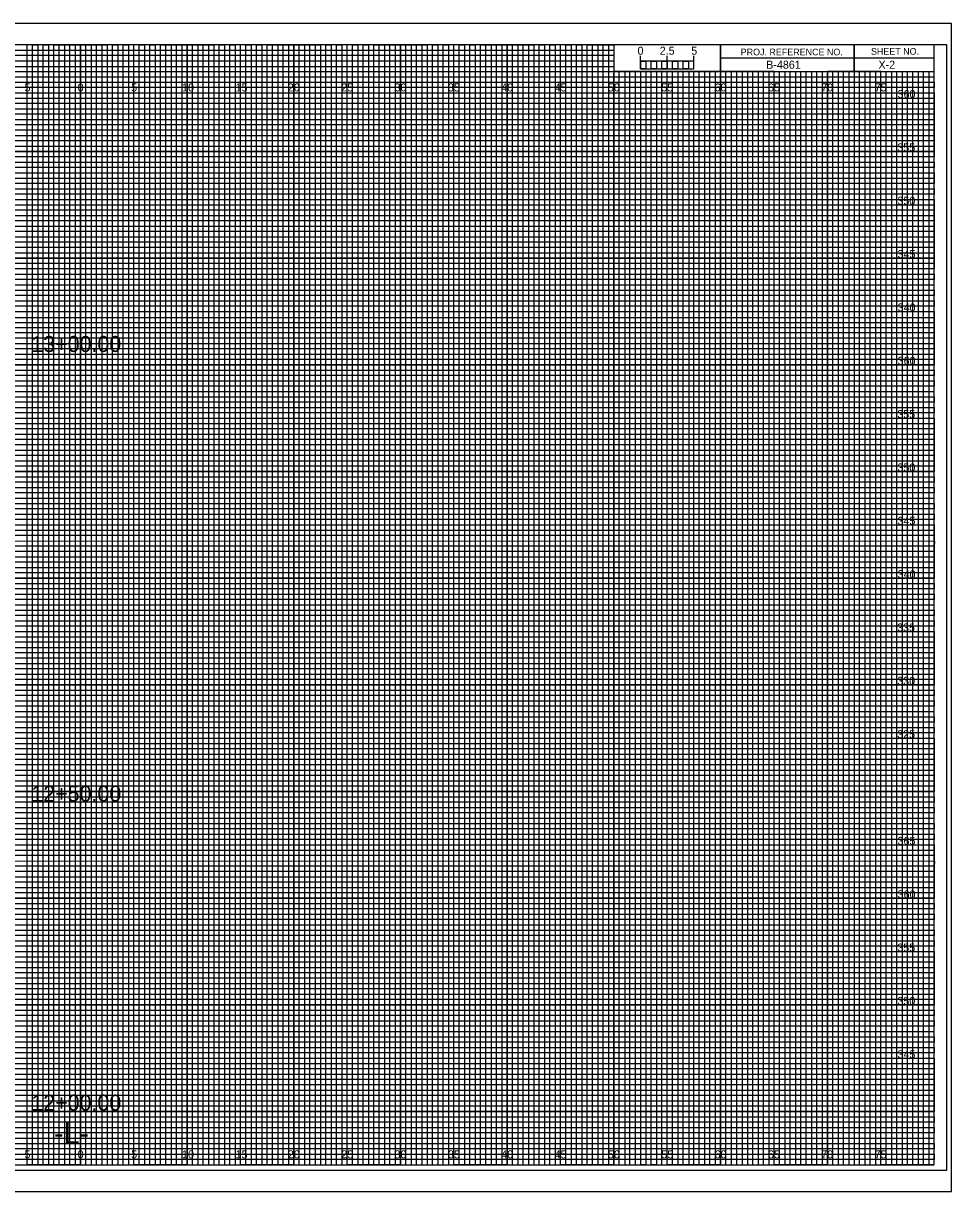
# Model space of a CAD drawing. Extents: x -7 to 266, y -5 to 437.
# Drawn here: x 74.6 to 161.7, y 107.5 to 217 of the extents above; entities that cross this region are included whole.
import ezdxf

# ---------------------------------------------------------------- set-up
doc = ezdxf.new("R2010")
doc.units = 0
for name, color, linetype in [('Exist XS Center Line Elevation Label', 7, 'Continuous'), ('Exist XS Ground Line', 7, 'Continuous'), ('Prop XS Dump Level', 7, 'Continuous'), ('Prop XS EOT Tick Mark', 7, 'Continuous'), ('Prop XS Finish Grade', 7, 'Continuous'), ('Prop XS Finish Grade Concrete', 7, 'Continuous'), ('Prop XS Finish Grade Earthwork', 7, 'Continuous'), ('Prop XS Finish Grade Pavement', 7, 'Continuous'), ('Prop XS Geopak Shape', 7, 'Continuous'), ('Prop XS Hydro Elevations', 7, 'Continuous'), ('Prop XS Pvmt Edge Slope', 7, 'Continuous'), ('Prop XS SE Text', 7, 'Continuous'), ('Prop XS Side Slope Text', 7, 'Continuous'), ('Prop XS SS Elevation Text', 7, 'Continuous'), ('Prop XS Subgrade Earthwork', 7, 'Continuous'), ('Prop XSC Text', 7, 'Continuous'), ('Typical Guardrail CELL', 7, 'Continuous')]:
    doc.layers.add(name, color=color, linetype=linetype)

msp = doc.modelspace()

# ---------------------------------------------------------------- linework, layer by layer
at = {"layer": 'Exist XS Center Line Elevation Label'}
for points in [[(72.5, 110), (77.5, 110), (77.5, 215), (82.5, 215), (82.5, 110), (87.5, 110), (87.5, 215), (92.5, 215), (92.5, 110), (97.5, 110), (97.5, 215), (102.5, 215), (102.5, 110), (107.5, 110), (107.5, 215), (112.5, 215), (112.5, 110), (117.5, 110), (117.5, 215), (122.5, 215), (122.5, 110), (127.5, 110), (127.5, 215), (129.97, 215), (130, 215), (130, 212.5), (132.5, 212.5), (132.5, 110), (137.5, 110), (137.5, 212.5), (142.5, 212.5), (142.5, 110), (147.5, 110), (147.5, 212.5), (152.5, 212.5), (152.5, 110), (157.5, 110), (157.5, 212.5)], [(0, 212.5), (137.5, 212.5)], [(0, 202.5), (160, 202.5), (160, 207.5), (0, 207.5)], [(0, 192.5), (160, 192.5), (160, 197.5), (0, 197.5)], [(0, 182.5), (160, 182.5), (160, 187.5), (0, 187.5)], [(0, 172.5), (160, 172.5), (160, 177.5), (0, 177.5)], [(0, 162.5), (160, 162.5), (160, 167.5), (0, 167.5)], [(0, 152.5), (160, 152.5), (160, 157.5), (0, 157.5)], [(0, 142.5), (160, 142.5), (160, 147.5), (0, 147.5)], [(0, 132.5), (160, 132.5), (160, 137.5), (0, 137.5)], [(0, 122.5), (160, 122.5), (160, 127.5), (0, 127.5)], [(0, 112.5), (160, 112.5), (160, 117.5), (0, 117.5)]]:
    msp.add_lwpolyline(points, dxfattribs=at)
at = {"layer": 'Exist XS Ground Line'}
for p, q in [((75, 215), (70, 215)), ((75, 110), (75, 215)), ((85, 215), (80, 215)), ((80, 215), (80, 110)), ((85, 110), (85, 215)), ((95, 215), (90, 215)), ((90, 215), (90, 110)), ((95, 110), (95, 215)), ((105, 215), (100, 215)), ((100, 215), (100, 110)), ((105, 110), (105, 215)), ((115, 215), (110, 215)), ((110, 215), (110, 110)), ((115, 110), (115, 215)), ((125, 215), (120, 215)), ((120, 215), (120, 110)), ((125, 110), (125, 215)), ((130, 215), (130, 110)), ((135, 110), (135, 212.5)), ((145, 212.5), (140, 212.5)), ((140, 212.5), (140, 110)), ((145, 110), (145, 212.5)), ((155, 212.5), (150, 212.5)), ((150, 212.5), (150, 110)), ((155, 110), (155, 212.5)), ((80, 110), (75, 110)), ((90, 110), (85, 110)), ((100, 110), (95, 110)), ((110, 110), (105, 110)), ((120, 110), (115, 110)), ((130, 110), (125, 110)), ((140, 110), (135, 110)), ((150, 110), (145, 110)), ((160, 110), (155, 110)), ((160, 110), (160, 110))]:
    msp.add_line(p, q, dxfattribs=at)
for points in [[(0, 210), (160, 210), (160, 205), (0, 205)], [(0, 200), (160, 200), (160, 195), (0, 195)], [(0, 190), (160, 190), (160, 185), (0, 185)], [(0, 180), (160, 180), (160, 175), (0, 175)], [(0, 170), (160, 170), (160, 165), (0, 165)], [(0, 160), (160, 160), (160, 155), (0, 155)], [(0, 150), (160, 150), (160, 145), (0, 145)], [(0, 140), (160, 140), (160, 135), (0, 135)], [(0, 130), (160, 130), (160, 125), (0, 125)], [(0, 120), (160, 120), (160, 115), (0, 115)]]:
    msp.add_lwpolyline(points, dxfattribs=at)
at = {"layer": 'Prop XS Finish Grade'}
for p, q in [((75, 110), (75, 215)), ((80, 110), (80, 215)), ((85, 110), (85, 215)), ((90, 110), (90, 215)), ((95, 110), (95, 215)), ((100, 110), (100, 215)), ((105, 110), (105, 215)), ((110, 110), (110, 215)), ((115, 110), (115, 215)), ((120, 110), (120, 215)), ((125, 110), (125, 215)), ((130, 110), (130, 212.34)), ((135, 110), (135, 212.34)), ((140, 110), (140, 212.34)), ((145, 110), (145, 212.34)), ((150, 110), (150, 212.34)), ((155, 110), (155, 212.34)), ((0, 210), (160, 210)), ((0, 205), (160, 205)), ((0, 200), (160, 200)), ((0, 195), (160, 195)), ((0, 190), (160, 190)), ((0, 185), (160, 185)), ((0, 180), (160, 180)), ((0, 175), (160, 175)), ((0, 170), (160, 170)), ((0, 165), (160, 165)), ((0, 160), (160, 160)), ((0, 155), (160, 155)), ((0, 150), (160, 150)), ((0, 145), (160, 145)), ((0, 140), (160, 140)), ((0, 135), (160, 135)), ((0, 130), (160, 130)), ((0, 125), (160, 125)), ((0, 120), (160, 120)), ((0, 115), (160, 115))]:
    msp.add_line(p, q, dxfattribs=at)
at = {"layer": 'Prop XS Finish Grade Earthwork'}
msp.add_lwpolyline([(-6.7, 107.5), (161.65, 107.5), (161.65, 217), (-6.7, 217)], close=True, dxfattribs=at)
at = {"layer": 'Prop XS Hydro Elevations'}
for p, q in [((152.5, 215), (152.5, 212.5)), ((152.5, 212.5), (152.5, 215)), ((160, 213.75), (140, 213.75)), ((140, 213.75), (140, 212.5)), ((140, 212.5), (160, 212.5))]:
    msp.add_line(p, q, dxfattribs=at)
for points in [[(160, 215), (0, 215), (0, 110), (160, 110)], [(140, 215), (130, 215), (130, 212.52), (140, 212.52)], [(160, 215), (140, 215), (140, 212.5), (160, 212.5)]]:
    msp.add_lwpolyline(points, close=True, dxfattribs=at)
at = {"layer": 'Prop XS Pvmt Edge Slope'}
msp.add_lwpolyline([(-5.4, 109.5), (161.2, 109.5), (161.2, 215), (-5.4, 215)], close=True, dxfattribs=at)
at = {"layer": 'Prop XS SE Text'}
for p, q in [((0, 214.5), (130, 214.5)), ((130, 213.99), (0, 213.99)), ((130, 214.5), (130, 213.99)), ((0, 213.5), (130, 213.5)), ((130, 212.94), (0, 212.94)), ((130, 213.5), (130, 212.94)), ((0, 212), (160, 212))]:
    msp.add_line(p, q, dxfattribs=at)
for points in [[(0, 211.5), (135, 211.5), (160, 211.5), (160, 211), (0, 211)], [(0, 210.5), (160, 210.5), (160, 209.5), (0, 209.5)], [(0, 209), (160, 209), (160, 208.5), (0, 208.49)], [(0, 208), (160, 208), (160, 207), (0, 207)], [(0, 206.5), (160, 206.5), (160, 206), (0, 206)], [(0, 205.5), (160, 205.5), (160, 204.5), (0, 204.5)], [(0, 204), (160, 204), (160, 203.5), (0, 203.5)], [(0, 203), (160, 203), (160, 202), (0, 202)], [(0, 201.5), (160, 201.5), (160, 201), (0, 201)], [(0, 200.5), (160, 200.5), (160, 199.5), (0, 199.5)], [(0, 199), (160, 199), (160, 198.5), (0, 198.5)], [(0, 198), (160, 198), (160, 196.97), (160, 196.5), (160, 196), (0, 196)], [(0, 197), (160, 197), (160, 196.5), (0, 196.5)], [(0, 195.5), (160, 195.5), (160, 194.5), (0, 194.52)], [(0, 194.52), (160, 194.5), (160, 194), (0, 194)], [(0, 193.5), (160, 193.5), (160, 193), (0, 193)], [(0, 192), (160, 192), (160, 191.5), (0, 191.5)], [(0, 191), (160, 191), (160, 190.5), (0, 190.5)], [(-0.04, 189.44), (160, 189.44), (160, 188.94), (-0.04, 188.94)], [(0, 188.5), (160, 188.5), (160, 188), (0, 188)], [(0, 187), (160, 187), (160, 186.5), (0, 186.5)], [(0, 186), (160, 186), (160, 185.5), (0, 185.5)], [(0, 184.5), (160, 184.5), (160, 184), (0, 184)], [(0, 183.5), (160, 183.5), (160, 183), (0, 183)], [(0, 182), (160, 182), (160, 181.5), (0, 181.5)], [(0, 181), (160, 181), (160, 180.5), (0, 180.5)], [(0, 179.5), (160, 179.5), (160, 178.99), (0, 179)], [(0, 178.5), (160, 178.5), (160, 178), (0, 178)], [(0, 177), (160, 177), (160, 176.5), (0, 176.5)], [(0, 176), (160, 176), (160, 175.5), (0, 175.5)], [(0, 174.5), (160, 174.5), (160, 174), (0, 174)], [(0, 173.5), (160, 173.5), (160, 173), (0, 173)], [(0, 172), (160, 172), (160, 171.5), (0, 171.5)], [(0, 171), (160, 171), (160, 170.5), (0, 170.5)], [(0, 169.5), (160, 169.5), (160, 169), (0, 169)], [(0, 168.5), (160.03, 168.46), (160, 168), (0, 168)], [(0, 167), (160, 167), (160, 166.5), (0, 166.5)], [(0, 166), (160, 166), (160, 165.5), (0, 165.5)], [(0, 164.5), (160, 164.5), (160, 164), (0, 164)], [(0, 163.5), (160, 163.5), (160, 163), (0, 163)], [(0, 162), (160, 162), (160, 161.5), (0, 161.5)], [(0, 161), (160, 161), (160, 160.5), (0, 160.5)], [(0, 159.5), (160, 159.5), (160, 159), (0, 159)], [(0, 158.5), (160, 158.5), (160, 158), (0, 158)], [(0, 157), (160, 157), (160, 156.5), (0, 156.5)], [(0, 156), (160, 156), (160, 155.5), (0, 155.5)], [(0, 154.5), (160, 154.5), (160, 154), (0, 154)], [(0, 153.5), (160, 153.5), (160, 153), (0, 153)], [(0, 152), (160, 152), (160, 151.5), (0, 151.5)], [(0, 151), (160, 151), (160, 150.5), (0, 150.5)], [(0, 149.5), (160, 149.5), (160, 148.99), (0, 149)], [(0, 148.5), (160, 148.5), (160, 148), (0, 148)], [(0, 147), (160, 147), (160, 146.5), (0, 146.5)], [(0, 146), (160, 146), (160, 145.5), (0, 145.5)], [(0, 144.5), (160, 144.5), (160, 144), (0, 144)], [(0, 143.5), (160, 143.5), (160, 143), (0, 143)], [(0, 142), (160, 142), (160, 141.5), (0, 141.5)], [(0, 141), (160, 141), (160, 140.5), (0, 140.5)], [(0, 139.5), (160, 139.5), (160, 139), (0, 139)], [(0, 138.5), (160.03, 138.46), (160, 138), (0, 138)], [(0, 137), (160, 137), (160, 136.5), (0, 136.5)], [(0, 136), (160, 136), (160, 135.5), (0, 135.5)], [(0, 134.5), (160, 134.5), (160, 134), (0, 134)], [(0, 133.5), (160, 133.5), (160, 133), (0, 133)], [(0, 132), (160, 132), (160, 131.5), (0, 131.5)], [(0, 131), (160, 131), (160, 130.5), (0, 130.5)], [(0, 129.5), (160, 129.5), (160, 129), (0, 129)], [(0, 128.5), (160, 128.5), (160, 128), (0, 128)], [(0, 127), (160, 127), (160, 126.5), (0, 126.5)], [(0, 126), (160, 126), (160, 125.5), (0, 125.5)], [(0, 124.5), (160, 124.5), (160, 124), (0, 124)], [(0, 123.5), (160, 123.5), (160, 123), (0, 123)], [(0, 122), (160, 122), (160, 121.5), (0, 121.5)], [(0, 121), (160, 121), (160, 120.5), (0, 120.5)], [(0, 119.5), (160, 119.5), (160, 119), (0, 119)], [(0, 118.5), (160, 118.5), (160, 118), (0, 118)], [(0, 117), (160, 117), (160, 116.5), (0, 116.5)], [(0, 116), (160, 116), (160, 115.5), (0, 115.5)], [(0, 114.5), (160, 114.5), (160, 114), (0, 114)], [(0, 113.5), (160, 113.5), (160, 113), (0, 113)], [(0, 112), (160, 112), (160, 111.5), (0, 111.5)], [(0, 111), (160, 111), (160, 110.5), (0, 110.5)]]:
    msp.add_lwpolyline(points, dxfattribs=at)
at = {"layer": 'Prop XS Side Slope Text'}
for p, q in [((132.5, 212.75), (132.5, 213.95)), ((132.5, 213.45), (132.5, 213.95)), ((135, 212.75), (135, 213.95)), ((137.5, 212.75), (137.5, 213.95)), ((137.5, 213.45), (137.5, 213.95))]:
    msp.add_line(p, q, dxfattribs=at)
for points in [[(137.5, 213.45), (132.5, 213.45), (132.5, 212.75), (137.5, 212.75)], [(132.5, 213.45), (133, 213.45), (133, 212.75), (132.5, 212.75)], [(133.5, 213.45), (134, 213.45), (134, 212.75), (133.5, 212.75)], [(134.5, 213.45), (135, 213.45), (135, 212.75), (134.5, 212.75)], [(135.5, 213.45), (136, 213.45), (136, 212.75), (135.5, 212.75)], [(136.5, 213.45), (137, 213.45), (137, 212.75), (136.5, 212.75)]]:
    msp.add_lwpolyline(points, close=True, dxfattribs=at)
at = {"layer": 'Prop XS SS Elevation Text'}
for p, q in [((133.5, 212.5), (133, 212.5)), ((133, 212.5), (133, 110)), ((133.5, 110), (133.5, 212.5)), ((134.5, 212.5), (134, 212.5)), ((134, 212.5), (134, 110)), ((134.5, 110), (134.5, 212.5)), ((133, 110), (132.5, 110)), ((134, 110), (133.5, 110))]:
    msp.add_line(p, q, dxfattribs=at)
for points in [[(75, 110), (75.5, 110), (75.5, 215), (76, 215), (76, 110)], [(76, 110), (76.5, 110), (76.5, 215), (77, 215), (77, 110)], [(77.5, 110), (78, 110), (78, 215), (78.5, 215), (78.5, 110)], [(78.5, 110), (79, 110), (79, 215), (79.5, 215), (79.5, 110)], [(80, 110), (80.5, 110), (80.5, 215), (81, 215), (81, 110)], [(81, 110), (81.5, 110), (81.5, 215), (82, 215), (82, 110)], [(82.5, 110), (83, 110), (83, 215), (83.5, 215), (83.5, 110)], [(83.5, 110), (84, 110), (84, 215), (84.5, 215), (84.5, 110)], [(85, 110), (85.5, 110), (85.5, 215), (86, 215), (86, 110)], [(86, 110), (86.5, 110), (86.5, 215), (87, 215), (87, 110)], [(87.5, 110), (88, 110), (88, 215), (88.5, 215), (88.5, 110)], [(88.5, 110), (89, 110), (89, 215), (89.5, 215), (89.5, 110)], [(90, 110), (90.5, 110), (90.5, 215), (91, 215), (91, 110)], [(91, 110), (91.5, 110), (91.5, 215), (92, 215), (92, 110)], [(92.5, 110), (93, 110), (93, 215), (93.5, 215), (93.5, 110)], [(93.5, 110), (94, 110), (94, 215), (94.5, 215), (94.5, 110)], [(95, 110), (95.5, 110), (95.5, 215), (96, 215), (96, 110)], [(96, 110), (96.5, 110), (96.5, 215), (97, 215), (97, 110)], [(97.5, 110), (98, 110), (98, 215), (98.5, 215), (98.5, 110)], [(98.5, 110), (99, 110), (99, 215), (99.5, 215), (99.5, 110)], [(100, 110), (100.5, 110), (100.5, 215), (101, 215), (101, 110)], [(101, 110), (101.5, 110), (101.5, 215), (102, 215), (102, 110)], [(102.5, 110), (103, 110), (103, 215), (103.5, 215), (103.5, 110)], [(103.5, 110), (104, 110), (104, 215), (104.5, 215), (104.5, 110)], [(105, 110), (105.5, 110), (105.5, 215), (106, 215), (106, 110)], [(106, 110), (106.5, 110), (106.5, 215), (107, 215), (107, 110)], [(107.5, 110), (108, 110), (108, 215), (108.5, 215), (108.5, 110)], [(108.5, 110), (109, 110), (109, 215), (109.5, 215), (109.5, 110)], [(110, 110), (110.5, 110), (110.5, 215), (111, 215), (111, 110)], [(111, 110), (111.5, 110), (111.5, 215), (112, 215), (112, 110)], [(112.5, 110), (113, 110), (113, 215), (113.5, 215), (113.5, 110)], [(113.5, 110), (114, 110), (114, 215), (114.5, 215), (114.5, 110)], [(115, 110), (115.5, 110), (115.5, 215), (116, 215), (116, 110)], [(116, 110), (116.5, 110), (116.5, 215), (117, 215), (117, 110)], [(117.5, 110), (118, 110), (118, 215), (118.5, 215), (118.5, 110)], [(118.5, 110), (119, 110), (119, 215), (119.5, 215), (119.5, 110)], [(120, 110), (120.5, 110), (120.5, 215), (121, 215), (121, 110)], [(121, 110), (121.5, 110), (121.5, 215), (122, 215), (122, 110)], [(122.5, 110), (123, 110), (123, 215), (123.5, 215), (123.5, 110)], [(123.5, 110), (124, 110), (124, 215), (124.5, 215), (124.5, 110)], [(125, 110), (125.5, 110), (125.5, 215), (126, 215), (126, 110)], [(126, 110), (126.5, 110), (126.5, 215), (127, 215), (127, 110)], [(127.5, 110), (128, 110), (128, 215), (128.5, 215), (128.5, 110)], [(128.5, 110), (129, 110), (129, 215), (129.5, 215), (129.5, 110)], [(130, 110), (130.5, 110), (130.5, 212.5), (131.01, 212.5), (131.01, 110)], [(131, 110), (131.5, 110), (131.5, 212.5), (132, 212.5), (132, 110)], [(135, 110), (135.49, 110), (135.49, 212.5), (136, 212.5), (136, 110)], [(136, 110), (136.5, 110), (136.5, 212.5), (137.03, 212.5), (137.03, 110)], [(137.5, 110), (138, 110), (138, 212.5), (138.5, 212.5), (138.5, 110)], [(138.5, 110), (139, 110), (139, 212.5), (139.5, 212.5), (139.5, 110)], [(140, 110), (140.5, 110), (140.5, 212.5), (141, 212.5), (141, 110)], [(141, 110), (141.5, 110), (141.5, 212.5), (142, 212.5), (142, 110)], [(142.5, 110), (143, 110), (143, 212.5), (143.5, 212.5), (143.5, 110)], [(143.5, 110), (144, 110), (144, 212.5), (144.5, 212.5), (144.5, 110)], [(145, 110), (145.5, 110), (145.5, 212.5), (146, 212.5), (146, 110)], [(146, 110), (146.5, 110), (146.5, 212.5), (147, 212.5), (147, 110)], [(147.5, 110), (148, 110), (148, 212.5), (148.5, 212.5), (148.5, 110)], [(148.5, 110), (149, 110), (149, 212.5), (149.5, 212.5), (149.5, 110)], [(150, 110), (150.5, 110), (150.5, 212.5), (151, 212.5), (151, 110)], [(151, 110), (151.5, 110), (151.5, 212.5), (152, 212.5), (152, 110)], [(152.5, 110), (153, 110), (153, 212.5), (153.5, 212.5), (153.5, 110)], [(153.5, 110), (154, 110), (154, 212.5), (154.5, 212.5), (154.5, 110)], [(155, 110), (155.5, 110), (155.5, 212.5), (156, 212.5), (156, 110)], [(156, 110), (156.5, 110), (156.5, 212.5), (157, 212.5), (157, 110)], [(157.5, 110), (158, 110), (158, 212.5), (158.5, 212.5), (158.5, 110)], [(158.5, 110), (159, 110), (159, 212.5), (159.5, 212.5), (159.5, 110)]]:
    msp.add_lwpolyline(points, dxfattribs=at)
at = {"layer": 'Prop XS Subgrade Earthwork'}
for p, q in [((161.65, 217), (-6.7, 217)), ((-6.7, 107.5), (161.65, 107.5))]:
    msp.add_line(p, q, dxfattribs=at)

# ---------------------------------------------------------------- texts
at = {"layer": 'Prop XS Dump Level'}
msp.add_text('-L-', height=2, dxfattribs=at).set_placement((77.53, 112))
at = {"layer": 'Prop XS EOT Tick Mark'}
msp.add_text('X-2', height=0.75, dxfattribs=at).set_placement((154.79, 212.75))
at = {"layer": 'Prop XS Finish Grade Concrete'}
for s, p in [('360', (156.59, 210)), ('355', (156.56, 205)), ('350', (156.57, 200)), ('345', (156.58, 195)), ('340', (156.59, 190)), ('360', (156.59, 185)), ('355', (156.56, 180)), ('350', (156.57, 175)), ('345', (156.58, 170)), ('340', (156.59, 165)), ('335', (156.54, 160)), ('330', (156.55, 155)), ('325', (156.55, 150)), ('365', (156.58, 140)), ('360', (156.59, 135)), ('355', (156.56, 130)), ('350', (156.57, 125)), ('345', (156.58, 120))]:
    msp.add_text(s, height=0.75, dxfattribs=at).set_placement(p)
at = {"layer": 'Prop XS Finish Grade Pavement'}
msp.add_text('B-4861', height=0.75, dxfattribs=at).set_placement((144.27, 212.75))
at = {"layer": 'Prop XS Geopak Shape'}
for s, p in [('2.5', (134.29, 214.06)), ('5', (137.24, 214.06))]:
    msp.add_text(s, height=0.75, dxfattribs=at).set_placement(p)
at = {"layer": 'Prop XS Hydro Elevations'}
for s, p in [('PROJ. REFERENCE NO.', (141.88, 214)), ('SHEET NO.', (154.09, 214.06))]:
    msp.add_text(s, height=0.625, dxfattribs=at).set_placement(p)
at = {"layer": 'Prop XS Side Slope Text'}
msp.add_text('0', height=0.75, dxfattribs=at).set_placement((132.21, 214.06))
at = {"layer": 'Prop XSC Text'}
for s, p in [('13+00.00', (75.39, 186.2)), ('12+50.00', (75.39, 144.06)), ('12+00.00', (75.39, 115.09))]:
    msp.add_text(s, height=1.5, dxfattribs=at).set_placement(p)
at = {"layer": 'Typical Guardrail CELL'}
for s, p in [('5', (74.74, 210.62)), ('0', (79.73, 210.62)), ('0', (79.73, 210.62)), ('5', (84.74, 210.62)), ('10', (89.52, 210.62)), ('15', (94.53, 210.62)), ('20', (99.43, 210.62)), ('25', (104.44, 210.62)), ('30', (109.43, 210.62)), ('35', (114.44, 210.62)), ('40', (119.43, 210.62)), ('45', (124.44, 210.62)), ('50', (129.43, 210.62)), ('55', (134.44, 210.62)), ('60', (139.43, 210.62)), ('65', (144.44, 210.62)), ('70', (149.43, 210.62)), ('75', (154.44, 210.62)), ('5', (74.74, 110.62)), ('0', (79.73, 110.62)), ('0', (79.73, 110.62)), ('5', (84.74, 110.62)), ('10', (89.52, 110.62)), ('15', (94.53, 110.62)), ('20', (99.43, 110.62)), ('25', (104.44, 110.62)), ('30', (109.43, 110.62)), ('35', (114.44, 110.62)), ('40', (119.43, 110.62)), ('45', (124.44, 110.62)), ('50', (129.43, 110.62)), ('55', (134.44, 110.62)), ('60', (139.43, 110.62)), ('65', (144.44, 110.62)), ('70', (149.43, 110.62)), ('75', (154.44, 110.62))]:
    msp.add_text(s, height=0.75, dxfattribs=at).set_placement(p)

doc.saveas('drawing.dxf')
